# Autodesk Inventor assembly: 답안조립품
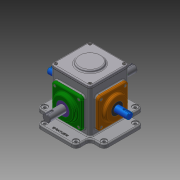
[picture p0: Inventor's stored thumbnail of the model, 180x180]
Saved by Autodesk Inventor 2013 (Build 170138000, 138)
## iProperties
Created: 2019-12
Part Number: 답안조립품
Document SubType Name: Assembly
Designer: Administrator
Author: Administrator
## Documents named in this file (16)
- C:\Users\Administrator\Desktop\391204V1008\답안조립품.iam
- C:\Users\Administrator\Desktop\391204V1008\개스킷.ipt
- C:\Users\Administrator\Desktop\391204V1008\메인베벨기어.ipt
- C:\Users\Administrator\Desktop\391204V1008\메인축.ipt
- C:\Users\Administrator\Desktop\391204V1008\메인커버.ipt
- C:\Users\Administrator\Desktop\391204V1008\베어링 6203.ipt
- C:\Users\Administrator\Desktop\391204V1008\베어링 6204.ipt
- C:\Users\Administrator\Desktop\391204V1008\본체.ipt
- C:\Users\Administrator\Desktop\391204V1008\볼트 M4.ipt
- C:\Users\Administrator\Desktop\391204V1008\상부커버.ipt
- C:\Users\Administrator\Desktop\391204V1008\서브베벨기어.ipt
- C:\Users\Administrator\Desktop\391204V1008\서브축.ipt
- C:\Users\Administrator\Desktop\391204V1008\서브커버.ipt
- C:\Users\Administrator\Desktop\391204V1008\오일 실 17 32 8.ipt
- C:\Users\Administrator\Desktop\391204V1008\오일 실 20 35 8.ipt
- C:\Users\Administrator\Desktop\391204V1008\키 4x4.ipt
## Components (1 placed, 1 different names)
1. 개스킷:1
